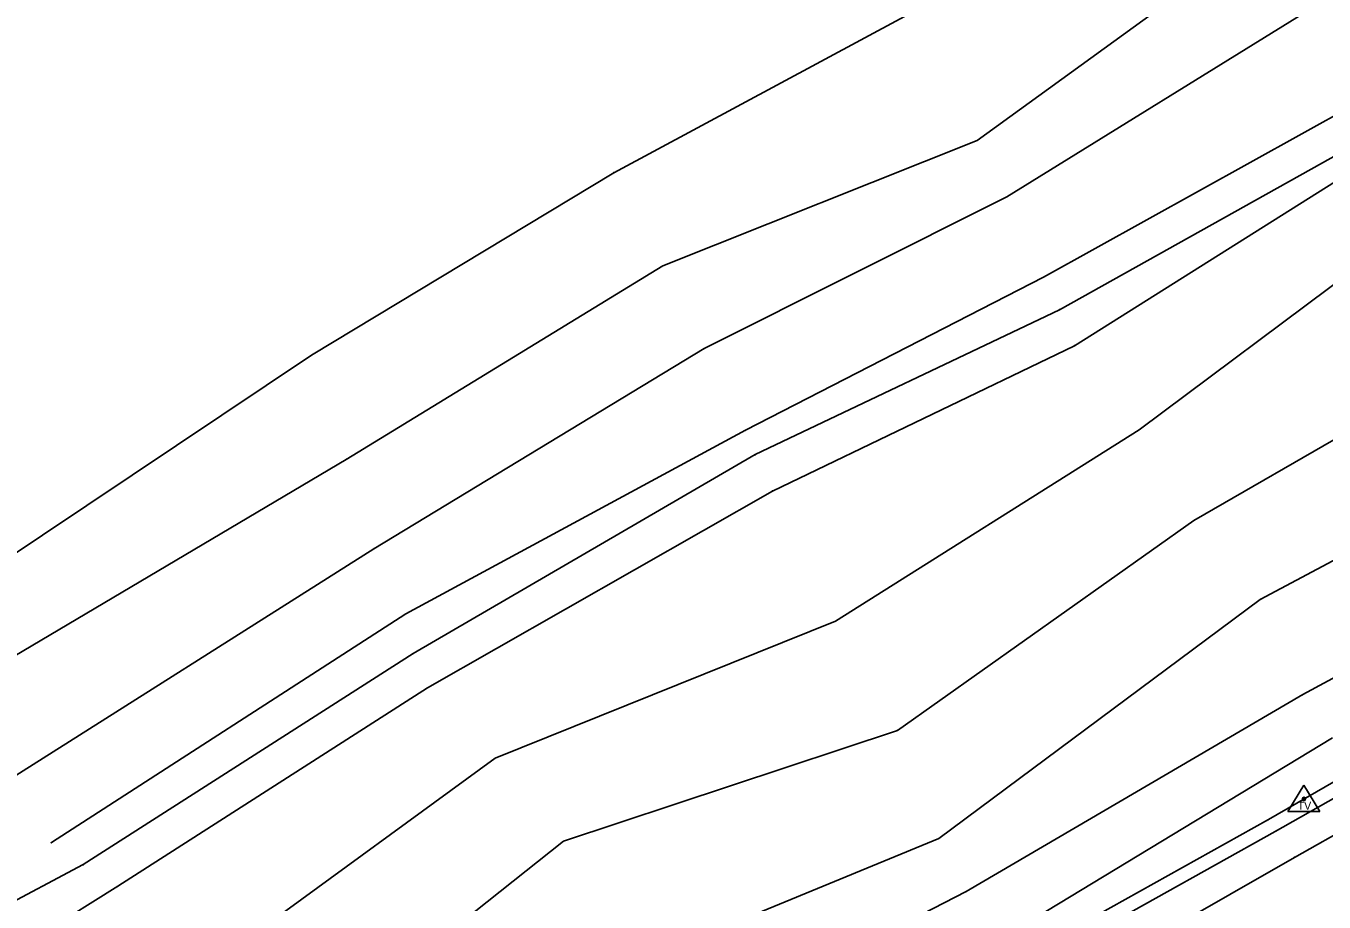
# Model space of a CAD drawing. Extents: x 1419505 to 1434054, y 1956910 to 1968644.
# Drawn here: x 1421225.5 to 1421468.9, y 1958046.7 to 1958210.9 of the extents above; entities that cross this region are included whole.
import ezdxf

# ---------------------------------------------------------------- set-up
doc = ezdxf.new("R2010")
doc.units = 0
for name, color, linetype in [('S_BREAKLINE', 7, 'Continuous'), ('S_DITCHLINE', 7, 'Continuous'), ('S_EDGE_PAVEMENT', 7, 'Continuous'), ('S_GRD_PT_SYM', 7, 'Continuous'), ('S_RDW_PT_SYM', 7, 'Continuous'), ('S_SECONDARY_CTL', 7, 'Continuous'), ('S_SHOULDER', 7, 'Continuous')]:
    doc.layers.add(name, color=color, linetype=linetype)

msp = doc.modelspace()

# ---------------------------------------------------------------- linework, layer by layer
at = {"layer": 'S_BREAKLINE'}
for p, q in [((1421403.8838, 1958189.3839), (1421459.3384, 1958229.5915)), ((1421335.7284, 1958183.3565), (1421390.225, 1958212.6364)), ((1421409.4212, 1958178.8292), (1421467.2219, 1958214.5585)), ((1421344.933, 1958165.8964), (1421403.8838, 1958189.3839)), ((1421422.101, 1958150.9424), (1421480.0398, 1958187.3868)), ((1421279.0638, 1958149.1603), (1421335.7284, 1958183.3565)), ((1421352.6715, 1958150.4034), (1421409.4212, 1958178.8292)), ((1421434.2408, 1958135.2014), (1421485.9391, 1958173.8169)), ((1421285.5852, 1958129.6361), (1421344.933, 1958165.8964)), ((1421189.379, 1958089.2904), (1421279.0638, 1958149.1603)), ((1421290.7855, 1958112.908), (1421352.6715, 1958150.4034)), ((1421365.4834, 1958123.7047), (1421422.101, 1958150.9424)), ((1421444.4695, 1958118.1743), (1421497.4829, 1958148.7993)), ((1421377.3281, 1958099.3131), (1421434.2408, 1958135.2014)), ((1421202.2138, 1958080.2829), (1421285.5852, 1958129.6361)), ((1421456.9493, 1958103.3984), (1421509.7497, 1958131.6082)), ((1421300.8412, 1958086.8313), (1421365.4834, 1958123.7047)), ((1421388.9169, 1958078.8588), (1421444.4695, 1958118.1743)), ((1421217.4568, 1958066.486), (1421290.7855, 1958112.908)), ((1421464.8878, 1958085.5622), (1421518.2212, 1958114.2681)), ((1421396.6844, 1958058.5895), (1421456.9493, 1958103.3984)), ((1421313.524, 1958073.6534), (1421377.3281, 1958099.3131)), ((1421458.4504, 1958062.1337), (1421509.2786, 1958091.5046)), ((1421242.7334, 1958049.6429), (1421300.8412, 1958086.8313)), ((1421401.7977, 1958048.6468), (1421464.8878, 1958085.5622)), ((1421326.2938, 1958058.0854), (1421388.9169, 1958078.8588)), ((1421407.2731, 1958039.2002), (1421470.4871, 1958077.4767)), ((1421255.6113, 1958031.4667), (1421313.524, 1958073.6534)), ((1421414.0325, 1958037.3861), (1421458.4504, 1958062.1337)), ((1421268.1031, 1958011.9765), (1421326.2938, 1958058.0854)), ((1421342.6309, 1958036.386), (1421396.6844, 1958058.5895)), ((1421174.331, 1958006.9011), (1421242.7334, 1958049.6429)), ((1421347.8112, 1958020.979), (1421401.7977, 1958048.6468))]:
    msp.add_line(p, q, dxfattribs=at)
at = {"layer": 'S_DITCHLINE'}
for p, q in [((1421416.3216, 1958163.7973), (1421475.4815, 1958196.6424)), ((1421419.2768, 1958157.6869), (1421478.4617, 1958190.744)), ((1421360.41, 1958135.0874), (1421416.3216, 1958163.7973)), ((1421362.2492, 1958130.5421), (1421419.2768, 1958157.6869)), ((1421296.7629, 1958100.6852), (1421360.41, 1958135.0874)), ((1421298.101, 1958093.2477), (1421362.2492, 1958130.5421)), ((1421230.3006, 1958057.8304), (1421296.7629, 1958100.6852)), ((1421236.269, 1958053.7072), (1421298.101, 1958093.2477)), ((1421167.9976, 1958017.4948), (1421236.269, 1958053.7072))]:
    msp.add_line(p, q, dxfattribs=at)
at = {"layer": 'S_EDGE_PAVEMENT'}
for p, q in [((1421463.3317, 1958055.0592), (1421513.7939, 1958083.4821)), ((1421419.2128, 1958029.8056), (1421463.3317, 1958055.0592))]:
    msp.add_line(p, q, dxfattribs=at)
at = {"layer": 'S_GRD_PT_SYM'}
for points in [[(1421403.8838, 1958189.3839), (1421403.8838, 1958189.4339), (1421403.8838, 1958189.3839), (1421403.8338, 1958189.3839), (1421403.8838, 1958189.3839), (1421403.8838, 1958189.3339), (1421403.8838, 1958189.3839), (1421403.9338, 1958189.3839)], [(1421335.7284, 1958183.3565), (1421335.7284, 1958183.4065), (1421335.7284, 1958183.3565), (1421335.6784, 1958183.3565), (1421335.7284, 1958183.3565), (1421335.7284, 1958183.3065), (1421335.7284, 1958183.3565), (1421335.7784, 1958183.3565)], [(1421409.4212, 1958178.8292), (1421409.4212, 1958178.8792), (1421409.4212, 1958178.8292), (1421409.3712, 1958178.8292), (1421409.4212, 1958178.8292), (1421409.4212, 1958178.7792), (1421409.4212, 1958178.8292), (1421409.4712, 1958178.8292)], [(1421344.933, 1958165.8964), (1421344.933, 1958165.9464), (1421344.933, 1958165.8964), (1421344.883, 1958165.8964), (1421344.933, 1958165.8964), (1421344.933, 1958165.8464), (1421344.933, 1958165.8964), (1421344.983, 1958165.8964)], [(1421416.3216, 1958163.7973), (1421416.3216, 1958163.8473), (1421416.3216, 1958163.7973), (1421416.2716, 1958163.7973), (1421416.3216, 1958163.7973), (1421416.3216, 1958163.7473), (1421416.3216, 1958163.7973), (1421416.3716, 1958163.7973)], [(1421419.2768, 1958157.6869), (1421419.2768, 1958157.7369), (1421419.2768, 1958157.6869), (1421419.2268, 1958157.6869), (1421419.2768, 1958157.6869), (1421419.2768, 1958157.6369), (1421419.2768, 1958157.6869), (1421419.3268, 1958157.6869)], [(1421279.0638, 1958149.1603), (1421279.0638, 1958149.2103), (1421279.0638, 1958149.1603), (1421279.0138, 1958149.1603), (1421279.0638, 1958149.1603), (1421279.0638, 1958149.1103), (1421279.0638, 1958149.1603), (1421279.1138, 1958149.1603)], [(1421352.6715, 1958150.4034), (1421352.6715, 1958150.4534), (1421352.6715, 1958150.4034), (1421352.6215, 1958150.4034), (1421352.6715, 1958150.4034), (1421352.6715, 1958150.3534), (1421352.6715, 1958150.4034), (1421352.7215, 1958150.4034)], [(1421422.101, 1958150.9424), (1421422.101, 1958150.9924), (1421422.101, 1958150.9424), (1421422.051, 1958150.9424), (1421422.101, 1958150.9424), (1421422.101, 1958150.8924), (1421422.101, 1958150.9424), (1421422.151, 1958150.9424)], [(1421360.41, 1958135.0874), (1421360.41, 1958135.1374), (1421360.41, 1958135.0874), (1421360.36, 1958135.0874), (1421360.41, 1958135.0874), (1421360.41, 1958135.0374), (1421360.41, 1958135.0874), (1421360.46, 1958135.0874)], [(1421434.2408, 1958135.2014), (1421434.2408, 1958135.2514), (1421434.2408, 1958135.2014), (1421434.1908, 1958135.2014), (1421434.2408, 1958135.2014), (1421434.2408, 1958135.1514), (1421434.2408, 1958135.2014), (1421434.2908, 1958135.2014)], [(1421285.5852, 1958129.6361), (1421285.5852, 1958129.6861), (1421285.5852, 1958129.6361), (1421285.5352, 1958129.6361), (1421285.5852, 1958129.6361), (1421285.5852, 1958129.5861), (1421285.5852, 1958129.6361), (1421285.6352, 1958129.6361)], [(1421362.2492, 1958130.5421), (1421362.2492, 1958130.5921), (1421362.2492, 1958130.5421), (1421362.1992, 1958130.5421), (1421362.2492, 1958130.5421), (1421362.2492, 1958130.4921), (1421362.2492, 1958130.5421), (1421362.2992, 1958130.5421)], [(1421365.4834, 1958123.7047), (1421365.4834, 1958123.7547), (1421365.4834, 1958123.7047), (1421365.4334, 1958123.7047), (1421365.4834, 1958123.7047), (1421365.4834, 1958123.6547), (1421365.4834, 1958123.7047), (1421365.5334, 1958123.7047)], [(1421444.4695, 1958118.1743), (1421444.4695, 1958118.2243), (1421444.4695, 1958118.1743), (1421444.4195, 1958118.1743), (1421444.4695, 1958118.1743), (1421444.4695, 1958118.1243), (1421444.4695, 1958118.1743), (1421444.5195, 1958118.1743)], [(1421290.7855, 1958112.908), (1421290.7855, 1958112.958), (1421290.7855, 1958112.908), (1421290.7355, 1958112.908), (1421290.7855, 1958112.908), (1421290.7855, 1958112.858), (1421290.7855, 1958112.908), (1421290.8355, 1958112.908)], [(1421456.9493, 1958103.3984), (1421456.9493, 1958103.4484), (1421456.9493, 1958103.3984), (1421456.8993, 1958103.3984), (1421456.9493, 1958103.3984), (1421456.9493, 1958103.3484), (1421456.9493, 1958103.3984), (1421456.9993, 1958103.3984)], [(1421296.7629, 1958100.6852), (1421296.7629, 1958100.7352), (1421296.7629, 1958100.6852), (1421296.7129, 1958100.6852), (1421296.7629, 1958100.6852), (1421296.7629, 1958100.6352), (1421296.7629, 1958100.6852), (1421296.8129, 1958100.6852)], [(1421377.3281, 1958099.3131), (1421377.3281, 1958099.3631), (1421377.3281, 1958099.3131), (1421377.2781, 1958099.3131), (1421377.3281, 1958099.3131), (1421377.3281, 1958099.2631), (1421377.3281, 1958099.3131), (1421377.3781, 1958099.3131)], [(1421298.101, 1958093.2477), (1421298.101, 1958093.2977), (1421298.101, 1958093.2477), (1421298.051, 1958093.2477), (1421298.101, 1958093.2477), (1421298.101, 1958093.1977), (1421298.101, 1958093.2477), (1421298.151, 1958093.2477)], [(1421300.8412, 1958086.8313), (1421300.8412, 1958086.8813), (1421300.8412, 1958086.8313), (1421300.7912, 1958086.8313), (1421300.8412, 1958086.8313), (1421300.8412, 1958086.7813), (1421300.8412, 1958086.8313), (1421300.8912, 1958086.8313)], [(1421464.8878, 1958085.5622), (1421464.8878, 1958085.6122), (1421464.8878, 1958085.5622), (1421464.8378, 1958085.5622), (1421464.8878, 1958085.5622), (1421464.8878, 1958085.5122), (1421464.8878, 1958085.5622), (1421464.9378, 1958085.5622)], [(1421388.9169, 1958078.8588), (1421388.9169, 1958078.9088), (1421388.9169, 1958078.8588), (1421388.8669, 1958078.8588), (1421388.9169, 1958078.8588), (1421388.9169, 1958078.8088), (1421388.9169, 1958078.8588), (1421388.9669, 1958078.8588)], [(1421313.524, 1958073.6534), (1421313.524, 1958073.7034), (1421313.524, 1958073.6534), (1421313.474, 1958073.6534), (1421313.524, 1958073.6534), (1421313.524, 1958073.6034), (1421313.524, 1958073.6534), (1421313.574, 1958073.6534)], [(1421458.4504, 1958062.1337), (1421458.4504, 1958062.1837), (1421458.4504, 1958062.1337), (1421458.4004, 1958062.1337), (1421458.4504, 1958062.1337), (1421458.4504, 1958062.0837), (1421458.4504, 1958062.1337), (1421458.5004, 1958062.1337)], [(1421230.3006, 1958057.8304), (1421230.3006, 1958057.8804), (1421230.3006, 1958057.8304), (1421230.2506, 1958057.8304), (1421230.3006, 1958057.8304), (1421230.3006, 1958057.7804), (1421230.3006, 1958057.8304), (1421230.3506, 1958057.8304)], [(1421326.2938, 1958058.0854), (1421326.2938, 1958058.1354), (1421326.2938, 1958058.0854), (1421326.2438, 1958058.0854), (1421326.2938, 1958058.0854), (1421326.2938, 1958058.0354), (1421326.2938, 1958058.0854), (1421326.3438, 1958058.0854)], [(1421396.6844, 1958058.5895), (1421396.6844, 1958058.6395), (1421396.6844, 1958058.5895), (1421396.6344, 1958058.5895), (1421396.6844, 1958058.5895), (1421396.6844, 1958058.5395), (1421396.6844, 1958058.5895), (1421396.7344, 1958058.5895)], [(1421236.269, 1958053.7072), (1421236.269, 1958053.7572), (1421236.269, 1958053.7072), (1421236.219, 1958053.7072), (1421236.269, 1958053.7072), (1421236.269, 1958053.6572), (1421236.269, 1958053.7072), (1421236.319, 1958053.7072)], [(1421242.7334, 1958049.6429), (1421242.7334, 1958049.6929), (1421242.7334, 1958049.6429), (1421242.6834, 1958049.6429), (1421242.7334, 1958049.6429), (1421242.7334, 1958049.5929), (1421242.7334, 1958049.6429), (1421242.7834, 1958049.6429)], [(1421401.7977, 1958048.6468), (1421401.7977, 1958048.6968), (1421401.7977, 1958048.6468), (1421401.7477, 1958048.6468), (1421401.7977, 1958048.6468), (1421401.7977, 1958048.5968), (1421401.7977, 1958048.6468), (1421401.8477, 1958048.6468)]]:
    msp.add_lwpolyline(points, dxfattribs=at)
at = {"layer": 'S_RDW_PT_SYM'}
for points in [[(1421459.7454, 1958059.9376), (1421459.7454, 1958059.9876), (1421459.7454, 1958059.9376), (1421459.6954, 1958059.9376), (1421459.7454, 1958059.9376), (1421459.7454, 1958059.8876), (1421459.7454, 1958059.9376), (1421459.7954, 1958059.9376)], [(1421463.3317, 1958055.0592), (1421463.3317, 1958055.1092), (1421463.3317, 1958055.0592), (1421463.2817, 1958055.0592), (1421463.3317, 1958055.0592), (1421463.3317, 1958055.0092), (1421463.3317, 1958055.0592), (1421463.3817, 1958055.0592)]]:
    msp.add_lwpolyline(points, dxfattribs=at)
at = {"layer": 'S_SECONDARY_CTL'}
for p, q in [((1421465.1358, 1958068.612), (1421462.1258, 1958063.6581)), ((1421465.1358, 1958068.612), (1421468.0831, 1958063.6581)), ((1421462.1258, 1958063.6581), (1421468.0831, 1958063.6581))]:
    msp.add_line(p, q, dxfattribs=at)
for radius in [0.3111, 0.1827, 0.1033]:
    msp.add_circle((1421465.1358, 1958066.0019), radius, dxfattribs=at)
at = {"layer": 'S_SHOULDER'}
for p, q in [((1421459.7454, 1958059.9376), (1421510.3417, 1958088.5224)), ((1421415.2846, 1958035.1059), (1421459.7454, 1958059.9376))]:
    msp.add_line(p, q, dxfattribs=at)

# ---------------------------------------------------------------- texts
at = {"layer": 'S_SECONDARY_CTL'}
msp.add_text('TV', height=1.5, rotation=360, dxfattribs=at).set_placement((1421463.9311, 1958063.9906))

doc.saveas('drawing.dxf')
